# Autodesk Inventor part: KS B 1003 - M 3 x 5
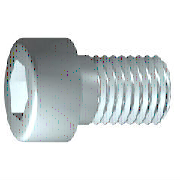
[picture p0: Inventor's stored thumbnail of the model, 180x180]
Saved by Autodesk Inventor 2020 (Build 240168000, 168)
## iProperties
Created: 2019-01
Part Number: KS B 1003 - M 3 x 5
Material: Acier, doux
Description: Vis à tôle à tête hexagonale
Document SubType Name: Modeling
Standard: KS B 1003
Designer: bruno
Standards Organization: KS
Language: fr-FR
Size Designation: M 3 x 5
Categories: <MemberInstance><Categories><Category DisplayName="Visserie" InternalName="e4da775c-781d-43d5-af7c-5136215cf5a6" Mnemonic="FSTN"><Category DisplayName="Vis" Int
Density: 7.85 g/cm^3
Appearance: Semi-poli
IsCustomPart: 0
Author: bruno
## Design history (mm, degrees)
sketch "Esquisse1"
  geometry: L1 (-0.867, 0)-(5, 0); L2 (5, 0)-(5, 1.5); L3 (5, 1.5)-(1.25, 1.5); L4 (1.25, 1.5)-(0.943, 1.5); L5 (0.943, 1.5)-(0, 1.5); L6 (0, 1.5)-(0, 2.75); L7 (0, 2.75)-(-3, 2.75); L8 (-3, 2.75)-(-3, 1.443); L9 (-3, 1.443)-(-1.7, 1.443); L10 (-1.7, 1.443)-(-0.867, 0); L11 (-4.6, 0)-(6.6, 0) reference; L12 (0, -0.55)-(0, 3.3) reference; L13 (1.25, 1.5)-(0, 1.5)
  constraints: 22 end point, 6 parallel, 2 collinear, 2 perpendicular, 1 horizontal, 1 point on line
  dimensions: "d1" = 3.75 distance from line of L3.end L2 (= GEL); "d2" = 0.30683 distance of L4.end L3.end (computed from GAL); "d3" = 3 distance between parallel lines of L8 L6 (= KOH); "d4" = 1.3 distance of L8.end L9.end (= INTI); "d5" = 60 deg angle of L10 L1; "d6" = 3 diameter of L3 L1 (= GD); "d7" = 3 diameter of L5 L1 (= BDM); "d8" = 2.88675 diameter of L9 L1 (= 1.1547 x SW); "d9" = 5.5 diameter of L7 L1 (= KOD); "d26" = 5 distance between parallel lines of L12 L2 (= NLG)
revolve "Corps" sketch "Esquisse1" stored, may be unused: angle "d10" = 90 deg
sketch "Esquisse2"
  geometry: L1 (0, -3.85)-(0, 3.85) reference; L2 (-3.85, 0)-(3.85, 0) reference; L3 (1.443, 0)-(0.722, -1.25); L4 (0.722, -1.25)-(-0.722, -1.25); L5 (-0.722, -1.25)-(-1.443, 0); L6 (-1.443, 0)-(-0.722, 1.25); L7 (-0.722, 1.25)-(0.722, 1.25); L8 (0.722, 1.25)-(1.443, 0); 2 further points
  constraints: 12 end point, 1 coincident, 1 horizontal alignment, 1 point on line, 12 other
extrude "Rainure" join sketch "Esquisse2" stored distance "d11" = 10; taper "d12" = 0 deg
workplane "Work Plane1"
fillet "Fillet2" dims "d30" = 0.1 (= R)
body "Solid1"
fillet "Congé1" dims "d17" = 0.3 (= RR)
feature "Filetage" dims "d13" = 3.75 (= GEL), "d14" = 0
chamfer "Chanfrein1" distance "d15" = 0.30673 (= -0.5 x SPD + 0.5 x GD); stored, may be unused: second distance "d16" = 0.30673 (= GUL), angle "d27" = 45 deg
other parameters: "GD" = 3 (= NND) [user parameter; used in 2 equation terms], "NLG" = 5 [user parameter; used in 1 equation term], "GEL" = 3.75 [user parameter; used in 2 equation terms], "KOD" = 5.5 [user parameter; used in 1 equation term], "KOH" = 3 [user parameter; used in 1 equation term], "INTI" = 1.3 [user parameter; used in 1 equation term], "GAL" = 0.30673 (= 0.61345 x PTC) [user parameter; used in 1 equation term], "GUL" = 0.30673 (= 0.61345 x PTC) [user parameter; used in 1 equation term], "BDM" = 3 (= NND) [user parameter; used in 1 equation term], "SW" = 2.5 [user parameter; used in 2 equation terms], "RR" = 0.3 [user parameter; used in 1 equation term], "SPD" = 2.38655 (= NND - 1.2269 x PTC) [user parameter; used in 1 equation term], "d19" = 0, "d28" = 0, "d29" = 0, "R" = 0.1 [user parameter; used in 1 equation term], "PHH" = 0.1 [user parameter], "GD1" = 2.38655 (= THREADDIA - 1.2269 x PTC) [user parameter], "THREADDIA" = 3 [user parameter; used in 1 equation term], "FAWI" = 45 deg [user parameter], "PTC" = 0.5 [user parameter; used in 5 equation terms], "NND" = 3 [user parameter; used in 3 equation terms], "TOA" = 30 deg [user parameter], "E0" = 2.8875 (= 1.155 x SW) [user parameter]
